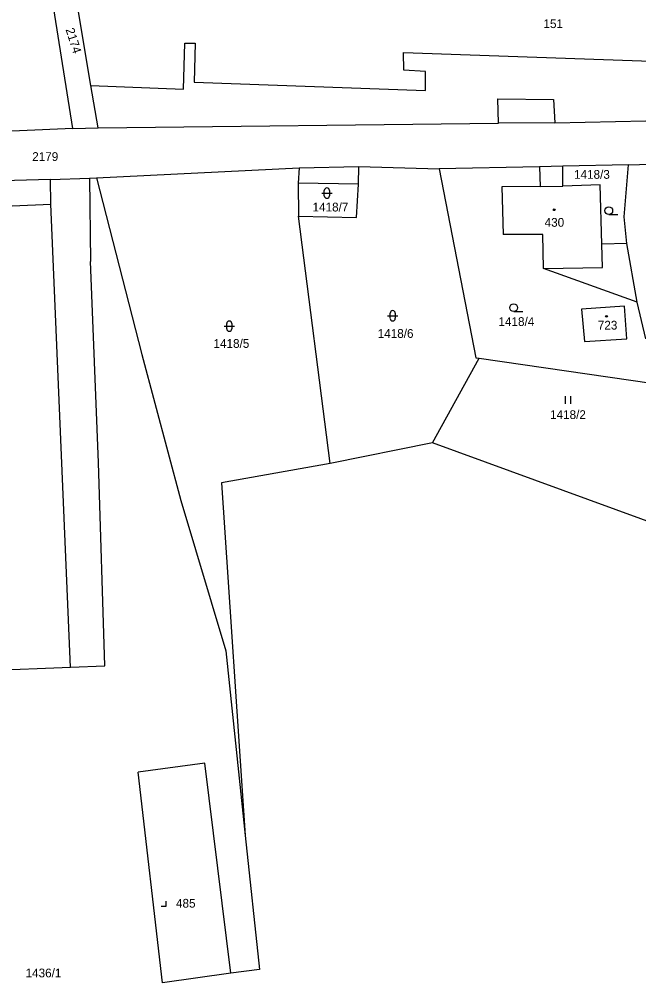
# Model space of a CAD drawing. Extents: x -717507 to -715515, y -957700 to -954941.
# Drawn here: x -716973.6 to -716853.4, y -957630.7 to -957443.7 of the extents above; entities that cross this region are included whole.
import ezdxf

# ---------------------------------------------------------------- set-up
doc = ezdxf.new("R2010")
doc.units = 0
for name, color, linetype in [('Hranice parcel', 7, 'Continuous'), ('Parcelní čísla', 7, 'Continuous'), ('Vnitřní kresba', 7, 'Continuous'), ('Značky budov', 7, 'Continuous'), ('Značky kultur', 7, 'Continuous')]:
    doc.layers.add(name, color=color, linetype=linetype)

msp = doc.modelspace()

# ---------------------------------------------------------------- linework, layer by layer
at = {"layer": 'Hranice parcel'}
for points in [[(-716963.15, -957464.91), (-716968.22, -957433.04)], [(-716959.67, -957456.55), (-716962.64, -957438.7)], [(-716958.27, -957464.78), (-716959.67, -957456.55)], [(-716958.27, -957464.78), (-716880.58, -957463.85)], [(-716869.66, -957463.78), (-716880.58, -957463.85)], [(-716869.66, -957463.78), (-716840.19, -957463.17)], [(-716963.15, -957464.91), (-717009.03, -957466.92)], [(-716963.15, -957464.91), (-716958.27, -957464.78)], [(-716855.35, -957471.94), (-716868.12, -957472.23)], [(-716856.19, -957482.06), (-716855.35, -957471.94)], [(-716855.35, -957471.94), (-716851.08, -957471.79)], [(-716958.61, -957474.49), (-716919.24, -957472.53)], [(-716919.24, -957472.53), (-716919.44, -957475.5)], [(-716919.24, -957472.53), (-716907.67, -957472.27)], [(-716907.73, -957475.67), (-716907.67, -957472.27)], [(-716907.67, -957472.27), (-716892.07, -957472.72)], [(-716872.63, -957472.3), (-716892.07, -957472.72)], [(-716892.07, -957472.72), (-716884.98, -957509.37)], [(-716868.12, -957472.23), (-716872.63, -957472.3)], [(-716872.63, -957472.3), (-716872.47, -957476.12)], [(-716868.07, -957476.06), (-716868.12, -957472.23)], [(-716967.49, -957474.81), (-717011.93, -957476.02)], [(-716967.49, -957474.81), (-716959.91, -957474.55)], [(-716967.46, -957479.6), (-716967.49, -957474.81)], [(-716959.91, -957474.55), (-716958.61, -957474.49)], [(-716959.91, -957474.55), (-716959.75, -957490.69)], [(-716958.61, -957474.49), (-716949.8, -957508.75)], [(-716919.44, -957475.5), (-716919.4, -957481.9)], [(-716908.1, -957482.19), (-716907.73, -957475.67)], [(-716872.47, -957476.12), (-716879.91, -957476.23)], [(-716879.91, -957476.23), (-716879.68, -957485.48)], [(-716860.82, -957475.85), (-716868.07, -957476.06)], [(-716860.53, -957487.32), (-716860.82, -957475.85)], [(-716991.53, -957480.6), (-716967.46, -957479.6)], [(-716919.4, -957481.9), (-716908.1, -957482.19)], [(-716913.26, -957529.9), (-716919.4, -957481.9)], [(-716855.67, -957487.24), (-716856.19, -957482.06)], [(-716871.96, -957485.47), (-716879.68, -957485.48)], [(-716871.84, -957492.09), (-716871.96, -957485.47)], [(-716855.67, -957487.24), (-716860.53, -957487.32)], [(-716853.66, -957498.59), (-716855.67, -957487.24)], [(-716958.21, -957529.71), (-716959.75, -957490.69)], [(-716853.66, -957498.59), (-716871.84, -957492.09)], [(-716856.14, -957499.37), (-716864.44, -957499.92)], [(-716864.44, -957499.92), (-716863.91, -957506.23)], [(-716855.69, -957505.68), (-716856.14, -957499.37)], [(-716851.97, -957505.73), (-716853.66, -957498.59)], [(-716863.91, -957506.23), (-716855.69, -957505.68)], [(-716949.8, -957508.75), (-716942.2, -957537.11)], [(-716884.98, -957509.37), (-716884.3, -957509.46)], [(-716893.37, -957525.87), (-716884.3, -957509.46)], [(-716884.3, -957509.46), (-716846.4, -957514.94)], [(-716893.37, -957525.87), (-716913.26, -957529.9)], [(-716837.89, -957546.13), (-716893.37, -957525.87)], [(-716956.97, -957569.14), (-716958.21, -957529.71)], [(-716913.26, -957529.9), (-716934.3, -957533.65)], [(-716934.3, -957533.65), (-716929.73, -957602.12)], [(-716942.2, -957537.11), (-716933.51, -957566.26)], [(-716933.51, -957566.26), (-716929.73, -957602.12)], [(-716963.62, -957569.41), (-716956.97, -957569.14)], [(-716996.16, -957570.71), (-716963.62, -957569.41)], [(-716937.55, -957588.04), (-716950.49, -957589.81)], [(-716945.79, -957630.66), (-716950.49, -957589.81)], [(-716932.54, -957628.82), (-716937.55, -957588.04)], [(-716929.73, -957602.12), (-716926.93, -957628.11)], [(-716932.54, -957628.82), (-716945.79, -957630.66)]]:
    msp.add_lwpolyline(points, dxfattribs=at)
at = {"layer": 'Vnitřní kresba'}
for points in [[(-716941.69, -957457.23), (-716941.47, -957448.31)], [(-716941.47, -957448.31), (-716939.45, -957448.31)], [(-716939.45, -957448.31), (-716939.61, -957455.9)], [(-716898.93, -957453.59), (-716898.99, -957450.17)], [(-716898.99, -957450.17), (-716847.25, -957451.97)], [(-716894.72, -957453.83), (-716898.93, -957453.59)], [(-716894.77, -957457.54), (-716894.72, -957453.83)], [(-716959.67, -957456.55), (-716941.69, -957457.23)], [(-716939.61, -957455.9), (-716894.77, -957457.54)], [(-716880.68, -957459.14), (-716869.88, -957459.26)], [(-716880.58, -957463.85), (-716880.68, -957459.14)], [(-716869.88, -957459.26), (-716869.66, -957463.78)], [(-716907.73, -957475.67), (-716919.44, -957475.5)], [(-716872.47, -957476.12), (-716868.07, -957476.06)], [(-716963.62, -957569.41), (-716967.46, -957479.6)], [(-716860.41, -957491.85), (-716860.53, -957487.32)], [(-716871.84, -957492.09), (-716860.41, -957491.85)], [(-716926.93, -957628.11), (-716932.54, -957628.82)]]:
    msp.add_lwpolyline(points, dxfattribs=at)
at = {"layer": 'Značky budov'}
for centre in [(-716869.75, -957480.65), (-716859.61, -957501.34)]:
    msp.add_circle(centre, 0.175, dxfattribs=at)
at = {"layer": 'Značky kultur'}
for points in [[(-716914.88, -957477.43), (-716912.88, -957477.43)], [(-716914.38, -957477.93), (-716914.38, -957476.93)], [(-716913.38, -957476.93), (-716913.38, -957477.93)], [(-716859.17, -957481.58), (-716857.42, -957481.58)], [(-716902.1, -957501.23), (-716900.1, -957501.23)], [(-716901.6, -957501.73), (-716901.6, -957500.73)], [(-716900.6, -957500.73), (-716900.6, -957501.73)], [(-716877.62, -957500.42), (-716875.87, -957500.42)], [(-716933.82, -957503.25), (-716931.82, -957503.25)], [(-716933.32, -957503.75), (-716933.32, -957502.75)], [(-716932.32, -957502.75), (-716932.32, -957503.75)], [(-716867.6, -957518.34), (-716867.6, -957516.84)], [(-716866.56, -957518.34), (-716866.56, -957516.84)], [(-716946.04, -957615.83), (-716945.04, -957615.83), (-716945.04, -957614.83)]]:
    msp.add_lwpolyline(points, dxfattribs=at)
for centre in [(-716859.17, -957480.83), (-716877.62, -957499.67)]:
    msp.add_circle(centre, 0.75, dxfattribs=at)
for centre, start, end in [((-716913.88, -957476.93), 0.101, 180.0014), ((-716913.88, -957477.93), 180.1024, 0.0029), ((-716901.1, -957500.73), 0.101, 180.0014), ((-716901.1, -957501.73), 180.1024, 0.0029), ((-716932.82, -957502.75), 0.101, 180.0014), ((-716932.82, -957503.75), 180.1024, 0.0029)]:
    msp.add_arc(centre, 0.5, start, end, dxfattribs=at)

# ---------------------------------------------------------------- texts
at = {"layer": 'Parcelní čísla'}
for s, p in [('151', (-716871.85, -957445.4)), ('2179', (-716971.06, -957471.19)), ('1418/3', (-716865.92, -957474.65)), ('1418/7', (-716916.66, -957480.99)), ('430', (-716871.62, -957483.96)), ('1418/4', (-716880.58, -957503.21)), ('1418/6', (-716904.02, -957505.52)), ('723', (-716861.3, -957503.91)), ('1418/5', (-716935.88, -957507.46)), ('1418/2', (-716870.57, -957521.27)), ('485', (-716943.16, -957616.09)), ('1436/1', (-716972.35, -957629.62))]:
    msp.add_text(s, height=1.7, dxfattribs=at).set_placement(p)
msp.add_text('2174', height=1.7, rotation=287.6023, dxfattribs=at).set_placement((-716964.6, -957445.68))

doc.saveas('drawing.dxf')
